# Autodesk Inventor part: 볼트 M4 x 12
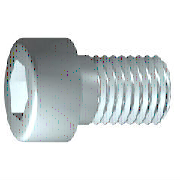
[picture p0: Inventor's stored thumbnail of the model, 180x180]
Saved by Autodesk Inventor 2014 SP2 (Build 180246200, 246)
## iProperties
IsCustomPart: 0
Created: 2012-02
Part Number: 볼트 M4 x 12
Material: 스테인리스강
Description: 6각 소켓 머리 캡 나사
Document SubType Name: Modeling
Standard: ISO 4762
Designer: mduedu
Standard Revision: Fourth edition 2004-03-01
Standards Organization: ISO
Language: ko-KR
Size Designation: M4 x 12
Categories: <MemberInstance><Categories><Category DisplayName="조임쇠" InternalName="e4da775c-781d-43d5-af7c-5136215cf5a6" Mnemonic="FSTN"><Category DisplayName="볼트" InternalN
Density: 8.08 g/cm^3
Mass: 2.29719 g
Surface Area: 3.30853 cm^2
Volume: 0.284306 cm^3
Appearance: 반광택
Author: mduedu
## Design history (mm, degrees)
sketch "스케치1"
  geometry: L1 (-1, 0)-(12, 0); L2 (12, 0)-(12, 2); L3 (12, 2)-(1.75, 2); L4 (1.75, 2)-(1.32, 2); L5 (1.32, 2)-(0, 2); L6 (0, 2)-(0, 3.5); L7 (0, 3.5)-(-4, 3.5); L8 (-4, 3.5)-(-4, 1.732); L9 (-4, 1.732)-(-2, 1.732); L10 (-2, 1.732)-(-1, 0); L11 (-7.2, 0)-(15.2, 0) reference; L12 (0, -0.7)-(0, 4.2) reference; L13 (1.75, 2)-(0, 2)
  constraints: 22 end point, 6 parallel, 2 collinear, 2 perpendicular, 1 horizontal, 1 point on line
  dimensions: "d1" = 10.25 distance from line of L3.end L2 (= GEL); "d2" = 0.42952 distance of L4.end L3.end (computed from GAL); "d3" = 4 distance between parallel lines of L8 L6 (= KOH); "d4" = 2 distance of L8.end L9.end (= INTI); "d5" = 60 deg angle of L10 L1; "d6" = 4 diameter of L3 L1 (= GD); "d7" = 4 diameter of L5 L1 (= BDM); "d8" = 3.4641 diameter of L9 L1 (= 1.1547 x SW); "d9" = 7 diameter of L7 L1 (= KOD); "d26" = 12 distance between parallel lines of L12 L2 (= NLG)
revolve "본체" sketch "스케치1" stored, may be unused: angle "d10" = 90 deg
sketch "스케치2"
  geometry: L1 (0, -4.9)-(0, 4.9) reference; L2 (-4.9, 0)-(4.9, 0) reference; L3 (1.732, 0)-(0.866, -1.5); L4 (0.866, -1.5)-(-0.866, -1.5); L5 (-0.866, -1.5)-(-1.732, 0); L6 (-1.732, 0)-(-0.866, 1.5); L7 (-0.866, 1.5)-(0.866, 1.5); L8 (0.866, 1.5)-(1.732, 0); 2 further points
  constraints: 12 end point, 1 coincident, 1 horizontal alignment, 1 point on line, 12 other
extrude "슬롯" join sketch "스케치2" stored distance "d11" = 10; taper "d12" = 0 deg
workplane "Work Plane1"
fillet "Fillet2" dims "d30" = 0.1 (= R)
body "Solid1"
fillet "모깎기1" dims "d17" = 0.4 (= RR)
feature "스레드" dims "d13" = 10.25 (= GEL), "d14" = 0
chamfer "모따기1" distance "d15" = 0.42941 (= -0.5 x SPD + 0.5 x GD); stored, may be unused: second distance "d16" = 0.42941 (= GUL), angle "d27" = 45 deg
other parameters: "GD" = 4 [user parameter; used in 2 equation terms], "NLG" = 12 [user parameter; used in 1 equation term], "GEL" = 10.25 [user parameter; used in 2 equation terms], "KOD" = 7 [user parameter; used in 1 equation term], "KOH" = 4 [user parameter; used in 1 equation term], "INTI" = 2 [user parameter; used in 1 equation term], "GAL" = 0.42941 (= 0.61345 x PTC) [user parameter; used in 1 equation term], "GUL" = 0.42941 (= 0.61345 x PTC) [user parameter; used in 1 equation term], "BDM" = 4 (= NND) [user parameter; used in 1 equation term], "SW" = 3 [user parameter; used in 2 equation terms], "RR" = 0.4 [user parameter; used in 1 equation term], "SPD" = 3.14117 (= NND - 1.2269 x PTC) [user parameter; used in 1 equation term], "d19" = 0, "d28" = 0, "d29" = 0, "R" = 0.1 [user parameter; used in 1 equation term], "TOA" = 30 deg [user parameter], "GD1" = 3.14117 (= THREADDIA - 1.2269 x PTC) [user parameter], "THREADDIA" = 4 [user parameter; used in 1 equation term], "FAWI" = 45 deg [user parameter], "TPU" = 14.28571 (computed from PTC) [user parameter], "PTC" = 0.7 [user parameter; used in 5 equation terms], "NND" = 4 [user parameter; used in 2 equation terms], "E0" = 3.465 (= 1.155 x SW) [user parameter]
